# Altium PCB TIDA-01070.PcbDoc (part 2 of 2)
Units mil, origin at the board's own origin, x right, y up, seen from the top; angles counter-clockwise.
Board outline 4200 x 3450 mil, 4 copper layers (Top Layer, Signal Layer 1, Signal Layer 2, Bottom Layer), stack 61.668 mil thick; 155 components, 69 nets, 375 pads, 212 vias.
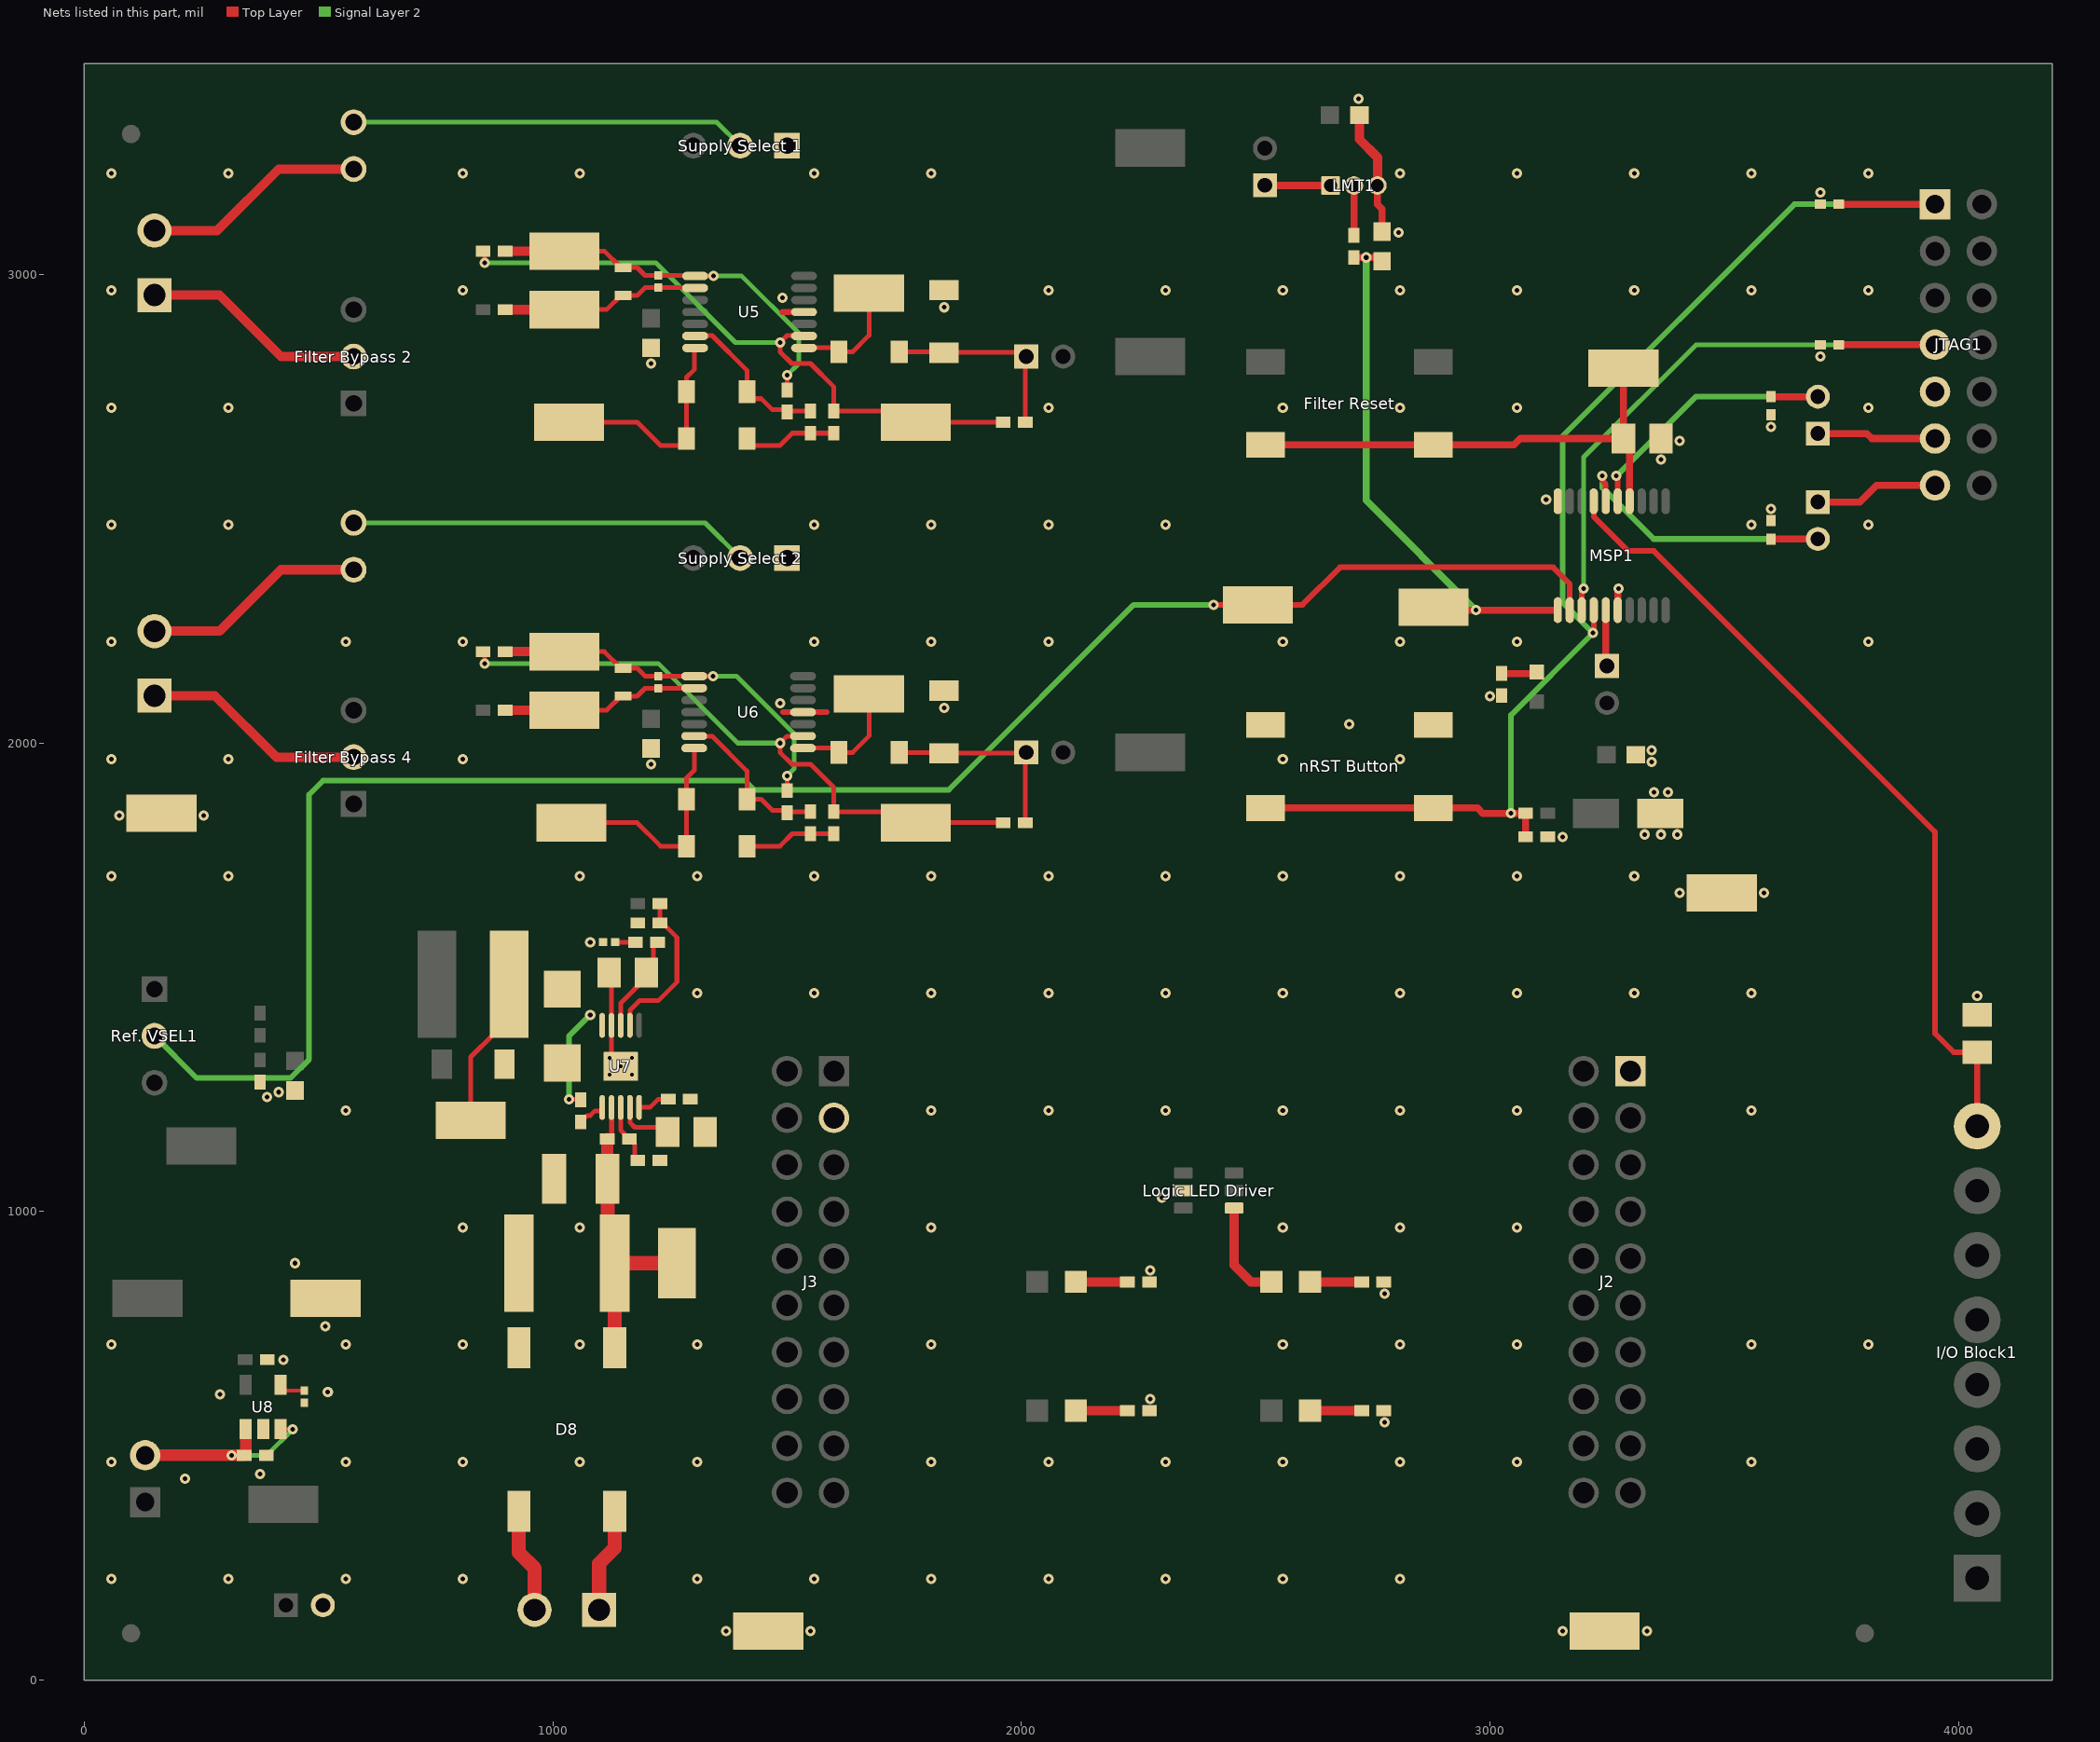
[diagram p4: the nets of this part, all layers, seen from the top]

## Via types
v1: diameter 22, hole 10, Top Layer to Bottom Layer, tented both sides, 206 vias
v2: diameter 19.68, hole 7.87, Top Layer to Bottom Layer, 5 vias
v3: diameter 36, hole 16, Top Layer to Bottom Layer, tented both sides, 1 vias

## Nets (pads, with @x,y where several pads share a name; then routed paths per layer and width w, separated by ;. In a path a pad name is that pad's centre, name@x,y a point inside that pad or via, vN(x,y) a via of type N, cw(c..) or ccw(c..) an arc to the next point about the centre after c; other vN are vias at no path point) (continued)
GND: "1.65V GND.1" "Logic LED Driver.2" "LP2985 GND.1" "nRST Button.1" "nRST Button.2" "Supply Select 1.1" "Supply Select 2.1" "TP GND.1" C1.2 C2.2 C3.1 C4.1 C5.1 C6.2 C7.1 C8.1 C9.1 C10.2 C12.1 C14.2 C16.2 C17.2 C18.2 C19.2 C20.2 C21.2 C22.2 D1.2 D8.2 J1.2 J2.1 J3.3 JTAG1.9 LMT1.3 MSP1.6 MSP1.20 MSP_GND.1 R2.2 R3.2 R4.2 R5.2 R7.2 R8.2 R24.1 R25.1 R30.1 R32.1 R33.1 TP3.1 U1.2 U2.2 U3.2 U4.2 U5.11 U6.11 U7.9 U7.11 U8.2 | length 663.9
  Top Layer w10: C19.2@1125.31,1510 1125.31,1329.69 v2(1145,1310)
  Top Layer w12: 1490,2920 U5.11@1536.14,2920 ; 1491,2066 1585,2066 ; v1@3272.8,2327.8 v1(3275,2330)
  Top Layer w15: LMT1.3@2760,3190 2760,3150 2770,3140 C5.1@2770,3091.5 ; MSP1.6@3272.8,2283.86 v1@3272.8,2327.8
  Top Layer w20: C4.1@2721.5,3340 2721.5,3288.5 2760,3250 LMT1.3@2760,3190
  other v1: 1370,105 1550,105 3155,105 3335,105 58,216 308,216 558,216 808,216 1308,216 1558,216 1808,216 2058,216 2308,216 2558,216 2808,216 215,430 375,440 58,466 558,466 808,466 1058,466 1308,466 1808,466 2058,466 2308,466 2558,466 2808,466 3058,466 3558,466 2775,550 2275,600 290,610 520,615 425,684 58,716 558,716 808,716 1058,716 1308,716 1808,716 2558,716 2808,716 3058,716 3558,716 3808,716 515,755 2775,825 2275,875 450,890 808,966 1058,966 1808,966 2558,966 2808,966 3058,966 2300,1030 558,1216 1808,1216 2058,1216 2308,1216 2558,1216 2808,1216 3058,1216 3558,1216 390,1245 415,1255 4040,1460 1308,1466 1558,1466 1808,1466 2058,1466 2308,1466 2558,1466 2808,1466 3058,1466 3308,1466 3558,1466 1080,1575 3405,1680 3585,1680 58,1716 308,1716 1058,1716 1308,1716 1558,1716 1808,1716 2058,1716 2308,1716 2558,1716 2808,1716 3058,1716 3308,1716 3155,1800 3330,1805 3365,1805 3400,1805 75,1845 255,1845 3350,1895 3380,1895 1210,1955 3345,1960 58,1966 308,1966 808,1966 2558,1966 2808,1966 3345,1985 2700,2040 1835,2075 1485,2085 3000,2100 58,2216 558,2216 808,2216 1558,2216 1808,2216 2058,2216 2558,2216 2808,2216 3058,2216 3808,2216 58,2466 308,2466 1558,2466 1808,2466 2058,2466 2308,2466 3558,2466 3808,2466 3600,2500 3120,2520 3365,2605 3405,2645 3600,2675 58,2716 308,2716 2058,2716 2558,2716 2808,2716 3058,2716 3808,2716 1210,2810 3705,2825 1835,2930 1490,2950 58,2966 808,2966 2058,2966 2308,2966 2558,2966 2808,2966 3058,2966 3308,2966 3558,2966 3808,2966 2805,3090 3705,3175 58,3216 308,3216 808,3216 1058,3216 1558,3216 1808,3216 2808,3216 3058,3216 3308,3216 3558,3216 3808,3216 2720,3375
  other v2: 1121.38,1292.28 1168.62,1292.28 1121.38,1327.72 1168.62,1327.72
NetC2_1: "Power Jumper1.2" C2.1 U8.1 U8.3 | length 447.2
  Top Layer w10: C2.1@341.38,480 C2.1@344.6,483.22 ; U8.3@419.4,535.76 420.16,535 v1(445,535)
  Top Layer w25: 130,480 v1(315,480) C2.1@341.38,480 ; C2.1@344.6,483.22 U8.1@344.6,535.76
  Signal Layer 2 w10: v1(315,480) 390,480 v1(445,535)
NetC10_1: "Filter Output 1.1" C10.1 D3.1 R13.2 | length 421.2
  Top Layer w10: D3.1@1739.47,2835 1823.62,2835 1825,2833.62 2009.25,2833.62 ; R13.2@2008.62,2685 2008.62,2832.99 2009.25,2833.62 ; 2010.63,2835 2009.25,2833.62
NetC11_1: C11.1 R10.1 R15.1 R16.2 TP18.1 U5.1 | length 829.3
  Top Layer w10: TP18.1@1025,3050 1110,3050 1145,3015 1180,3015 1197.01,2997.99 C11.1@1225,2997.99 1225.22,2997.77 U5.1@1301.86,2997.77 ; U5.1@1303.86,2996.77 v1(1343.23,2996.77) v1@1345,2995 ; R10.1@1500,2755 v1(1500,2785)
  Top Layer w20: R15.1@898.62,3050 TP18.1@1025,3050
  Signal Layer 2 w10: v1(1343.23,2996.77) 1403.23,2996.77 1525,2875 1525,2810 v1(1500,2785)
NetC11_2: C11.2 R14.2 R16.1 TP19.1 U5.2 | length 422.8
  Top Layer w10: TP19.1@1025,2925 1115,2925 1145,2955 1180,2955 1197.01,2972.01 C11.2@1225,2972.01 1301.68,2972.01 U5.2@1301.86,2972.18
  Top Layer w20: R14.2@898.62,2925 TP19.1@1025,2925
NetC13_1: C13.1 U7.1 | length 54.8
  Top Layer w10: C13.1@1060,1191.38 1073.62,1205 1080,1205 1090,1215 U7.1@1105,1215
NetC13_2: C13.2 D1.1 L1.1 TP2.1 U7.10 | length 429.9
  Top Layer w10: TP2.1@825,1195 825,1330 L1.1@875,1380 ; v1(1035,1240) 1058.62,1240 C13.2@1060,1238.62
  Signal Layer 2 w12: v1(1035,1240) 1035,1375 v1(1080,1420)
NetC14_1: "Filter Output 2.1" C14.1 D5.1 R20.2 | length 421.2
  Top Layer w10: D5.1@1739.47,1980 1823.62,1980 1825,1978.62 2009.25,1978.62 ; R20.2@2008.62,1830 2008.62,1977.99 2009.25,1978.62 ; 2010.63,1980 2009.25,1978.62
NetC15_1: C15.1 R17.1 R22.1 R26.2 TP23.1 U6.1 | length 814.6
  Top Layer w10: TP23.1@1025,2195 1110,2195 1145,2160 1180,2160 1197.01,2142.99 C15.1@1225,2142.99 1225.22,2142.77 U6.1@1301.86,2142.77 v1(1342.23,2142.77) v1@1345,2140 ; R17.1@1500,1903.62 R17.1@1501.38,1905 ; R17.1@1500,1906.38 v1(1500,1930)
  Top Layer w20: R22.1@898.62,2195 TP23.1@1025,2195
  Signal Layer 2 w10: v1(1342.23,2142.77) 1392.23,2142.77 1515,2020 1515,1945 v1(1500,1930)
NetC15_2: C15.2 R21.1 R26.1 TP24.1 U6.2 | length 422.8
  Top Layer w10: TP24.1@1025,2070 1115,2070 1145,2100 1180,2100 1197.01,2117.01 C15.2@1225,2117.01 1301.68,2117.01 U6.2@1301.86,2117.18
  Top Layer w20: R21.1@898.62,2070 TP24.1@1025,2070
NetC17_1: C17.1 C22.1 D8.1 R29.2 TP1.1 U7.2 | length 655.9
  Top Layer w10: C17.1@1116.38,1070.71 C17.1@1117.09,1070 ; R29.2@1116.38,1155 R29.2@1125.31,1163.94 ; C22.1@1117.09,905.28 C22.1@1132.36,890
  Top Layer w11: R29.2@1125.31,1163.94 U7.2@1125.31,1222.4
  Top Layer w25: C17.1@1116.38,1070.71 R29.2@1116.38,1155
  Top Layer w30: C22.1@1117.09,905.28 C17.1@1117.09,1070 ; D8.1@1132.36,709.5 C22.1@1132.36,890 TP1.1@1265,890
NetC18_1: C18.1 U7.4 | length 118.7
  Top Layer w10: U7.4@1164.68,1222.4 1164.68,1190.32 1175,1180 1240,1180 C18.1@1245,1185
NetC19_1: C19.1 R31.2 U7.8 | length 215
  Top Layer w10: U7.8@1145,1397.6 1145,1445 1200,1500 C19.1@1200,1510 1215,1525 1215,1575 R31.2@1223.62,1575
NetC20_1: C20.1 R31.1 | length 43.4
  Top Layer w10: C20.1@1132.99,1575 R31.1@1176.38,1575
NetC21_1: C21.1 U8.4 | length 55.7
  Top Layer w8: U8.4@419.4,630.24 431.65,617.99 C21.1@470,617.99
NetD2_1: D2.1 R10.2 R11.1 U5.6 | length 350.4
  Top Layer w10: U5.6@1301.86,2869.82 1340.18,2869.82 1414.47,2795.53 1414.47,2735 1445,2735 1468.62,2711.38 1500,2711.38 1502.76,2708.62 R11.1@1550,2708.62
NetD2_2: D2.2 D4.1 TP15.1 U5.7 | length 422.2
  Top Layer w10: TP15.1@1100,2685 1180,2685 1230,2635 1285.53,2635 1285.53,2735 1285.53,2780.53 1301.86,2796.86 U5.7@1301.86,2844.23
NetD3_2: D3.2 TP16.1 U5.8 | length 249.2
  Top Layer w10: U5.8@1534.14,2844.23 1601.3,2844.23 D3.2@1610.53,2835 1640,2835 1675,2870 TP16.1@1675,2960
NetD4_2: D4.2 R11.2 R12.1 | length 196.5
  Top Layer w10: D4.2@1414.47,2635 1485,2635 1511.38,2661.38 R12.1@1600,2661.38
NetD5_2: D5.2 TP21.1 U6.8 | length 249.2
  Top Layer w10: U6.8@1534.14,1989.23 1601.3,1989.23 D5.2@1610.53,1980 1640,1980 1675,2015 TP21.1@1675,2105
NetD6_1: D6.1 R17.2 R18.1 U6.6 | length 350.4
  Top Layer w10: U6.6@1301.86,2014.82 1340.18,2014.82 1414.47,1940.53 D6.1@1414.47,1880 1445,1880 1468.62,1856.38 1500,1856.38 1502.76,1853.62 R18.1@1550,1853.62
NetD6_2: D6.2 D7.1 TP20.1 U6.7 | length 422.2
  Top Layer w10: TP20.1@1100,1830 1180,1830 1230,1780 D7.1@1285.53,1780 D6.2@1285.53,1880 1285.53,1925.53 1301.86,1941.86 U6.7@1301.86,1989.23
NetD7_2: D7.2 R18.2 R19.1 | length 196.5
  Top Layer w10: D7.2@1414.47,1780 1485,1780 1511.38,1806.38 R19.1@1600,1806.38
NetD8_3: "Power Terminal Header1.2" D8.3 | length 224.4
  Top Layer w30: D8.3@927.64,360.5 927.64,272.36 961.1,238.9 961.1,150
NetD8_4: "Power Terminal Header1.1" D8.4 | length 224.4
  Top Layer w30: 1098.9,150 1098.9,248.9 1132.36,282.36 D8.4@1132.36,360.5
"NetDirty Coil LED1_2": "Dirty Coil LED1.2" R4.1 | length 110
  Top Layer w20: 2116.34,575 R4.1@2226.38,575
"NetDirty Filter LED1_2": "Dirty Filter LED1.2" R5.1 | length 110
  Top Layer w20: 2616.34,575 R5.1@2726.38,575
"NetFilter Bypass 1_2": "Filter Bypass 1.2" "Supply Select 1.2" | length 845.7
  Signal Layer 2 w10: 575,3325 1350,3325 1400,3275
"NetFilter Bypass 3_2": "Filter Bypass 3.2" "Supply Select 2.2" | length 856.1
  Signal Layer 2 w10: 575,2470 1325,2470 1400,2395
"NetFilter Reset_1": "Filter Reset.1" "Filter Reset.2" "Set Filter.1" MSP1.14 R24.2 | length 1059.2
  Top Layer w15: 2520.87,2636.42 2879.13,2636.42 3051.42,2636.42 3065,2650 R24.2@3285,2650 ; 3285,2800 R24.2@3285,2650 ; MSP1.14@3298.39,2516.14 3298.39,2636.61 R24.2@3285,2650
NetLMT1_1: "LMT84 V+.1" LMT1.1 | length 140.3
  Top Layer w15: 2520,3190.63 2520.63,3190 LMT1.1@2660,3190
NetLMT1_2: LMT1.2 R6.1 | length 106.4
  Top Layer w15: R6.1@2710,3083.62 LMT1.2@2710,3190
"NetLow Temp LED1_2": "Low Temp LED1.2" R3.1 | length 110
  Top Layer w20: 2116.34,850 R3.1@2226.38,850
NetMSP1_5: "MSP V+.1" MSP1.5 | length 120.6
  Top Layer w15: MSP1.5@3247.2,2283.86 3247.2,2167.17 3250,2164.37
NetPower_1: Power.1 R8.1 | length 76.2
  Top Layer w15: R8.1@3025,2148.62 3097.13,2148.62 Power.1@3100,2151.5
NetR7_1: "System Ok LED1.2" R7.1 | length 110
  Top Layer w20: 2616.34,850 R7.1@2726.38,850
NetR12_2: R12.2 R13.1 R15.2 TP17.1 U5.9 | length 1370.8
  Top Layer w10: R15.2@851.38,3050 855,3046.38 v1(855,3025) ; U5.9@1534.14,2869.82 1499.82,2869.82 v1(1485,2855) 1485,2835 1510,2810 1550,2810 1600,2760 R12.2@1600,2708.62 1751.38,2708.62 TP17.1@1775,2685 R13.1@1961.38,2685
  Signal Layer 2 w10: v1(855,3025) 1220,3025 1390,2855 v1(1485,2855)
NetR19_2: R19.2 R20.1 R22.2 TP22.1 U6.9 | length 1370.8
  Top Layer w10: R22.2@851.38,2195 855,2191.38 v1(855,2170) ; U6.9@1534.14,2014.82 1499.82,2014.82 v1(1485,2000) 1485,1980 1510,1955 1550,1955 1600,1905 R19.2@1600,1853.62 1751.38,1853.62 TP22.1@1775,1830 R20.1@1961.38,1830
  Signal Layer 2 w10: v1(855,2170) 1225,2170 1395,2000 v1(1485,2000)
NetR28_1: R28.1 R30.2 U7.7 | length 341.2
  Top Layer w10: U7.7@1164.68,1397.6 1164.68,1429.68 1185,1450 1225,1450 1265,1490 1265,1585 1235,1615 1228.62,1615 R28.1@1228.62,1655
NetR29_1: R29.1 R32.2 U7.3 | length 127.5
  Top Layer w10: U7.3@1145,1222.4 1145,1173.62 R29.1@1163.62,1155 1175,1143.62 1175,1116.38 R32.2@1181.38,1110
NetR33_2: R33.2 U7.5 | length 69.3
  Top Layer w10: U7.5@1184.37,1222.4 1207.4,1222.4 1225,1240 R33.2@1246.38,1240
NRST: "nRST Button.3" "nRST Button.4" C8.2 JTAG1.1 MSP1.4 R9.1 U4.1 | length 2769.5
  Top Layer w12: v1@3221.61,2236.61 MSP1.4@3221.61,2283.86
  Top Layer w15: 2520.87,1861.42 2879.13,1861.42 2973.58,1861.42 2985,1850 R9.1@3076.38,1850 C8.2@3076.38,1800 ; v1(3220,2235) v1@3221.61,2236.61 ; U4.1@3744.69,3150 JTAG1.1@3950,3150
  Signal Layer 2 w12: v1(3045,1850) 3045,2060 v1(3220,2235) 3155,2300 3155,2655 3650,3150 JTAG1.1@3950,3150
REFERENCE_SELECTOR: "Ref. VSEL1.2" MSP1.2 Reference.1 | length 3927.1
  Top Layer w12: v1(2410,2295) Reference.1@2505,2295 2600,2295 2680,2375 3135,2375 3170.43,2339.57 MSP1.2@3170.43,2283.86
  Signal Layer 2 w12: 150,1375 240,1285 440,1285 480,1325 480,1890 510,1920 1410,1920 1430,1900 1845,1900 2240,2295 2310,2295 v1(2410,2295)
SENSOR_OUT_1: "External Sensor Terminal1.2" "Filter Bypass 1.1" | length 479.3
  Top Layer w20: 150,3093.9 283.9,3093.9 415,3225 575,3225
SENSOR_OUT_2: "External Sensor Terminal2.2" "Filter Bypass 3.1" | length 479.3
  Top Layer w20: 150,2238.9 288.9,2238.9 420,2370 575,2370
SENSOR_RETURN_1: "External Sensor Terminal1.1" "Filter Bypass 2.2" | length 479.3
  Top Layer w20: 150,2956.1 288.9,2956.1 420,2825 575,2825
SENSOR_RETURN_2: "External Sensor Terminal2.1" "Filter Bypass 4.2" | length 479.3
  Top Layer w20: 150,2101.1 278.9,2101.1 410,1970 575,1970
SYSTEM_OK_OUT: "Logic LED Driver.4" "System Ok LED1.1" | length 216.1
  Top Layer w20: 2454.13,1007.6 2454.13,885.87 2490,850 2533.66,850
SYSTEM_ON: "I/O Block1.8" MSP1.17 R25.2 | length 1734.4
  Top Layer w12: MSP1.17@3221.61,2516.14 3221.61,2483.39 3295,2410 3350,2410 3950,1810 3950,1380 3990,1340 R25.2@4040,1340 4040,1182.28
TEMP_SENSOR: C5.2 MSP1.1 R6.2 Temp.1 | length 1180.1
  Top Layer w15: R6.2@2710,3036.38 v1(2736.06,3036.38) 2762.13,3036.38 C5.2@2770,3028.5 ; Temp.1@2880,2290 2886.14,2283.86 v1(2970,2283.86) MSP1.1@3144.84,2283.86
  Signal Layer 2 w15: v1(2736.06,3036.38) 2736.06,2517.8 v1(2970,2283.86)
TEST: JTAG1.7 MSP1.3 U3.1 | length 1382.5
  Top Layer w10: v1@3196.02,2326.02 v1(3200,2330)
  Top Layer w12: MSP1.3@3196.02,2283.86 v1@3196.02,2326.02
  Top Layer w15: U3.1@3744.69,2850 JTAG1.7@3950,2850
  Signal Layer 2 w10: v1(3200,2330) 3200,2610 3440,2850 JTAG1.7@3950,2850
UART_IN: JTAG1.13 UART_RX_Jumper1.1 | length 264.8
  Top Layer w15: UART_RX_Jumper1.1@3700,2514.37 3789.37,2514.37 3825,2550 JTAG1.13@3950,2550
UART_OUT: JTAG1.11 UART_TX_Jumper1.1 | length 254.4
  Top Layer w15: UART_TX_Jumper1.1@3700,2660.63 3804.37,2660.63 3815,2650 JTAG1.11@3950,2650
UART_RX: MSP1.16 U1.1 UART_RX_Jumper1.2 | length 688.2
  Top Layer w12: v1(3240,2570) 3240,2560 3247.2,2552.8 MSP1.16@3247.2,2516.14 ; U1.1@3609.37,2435 3610,2435.63
  Top Layer w15: U1.1@3600,2435.32 3600.31,2435.63 3610,2435.63 UART_RX_Jumper1.2@3700,2435.63
  Signal Layer 2 w12: v1(3240,2570) 3240,2545 3349.37,2435.63 UART_RX_Jumper1.2@3700,2435.63
UART_TX: MSP1.15 U2.1 UART_TX_Jumper1.2 | length 655.3
  Top Layer w12: v1(3270,2570) 3272.8,2567.2 MSP1.15@3272.8,2516.14
  Top Layer w15: U2.1@3600,2739.69 3600.31,2739.37 UART_TX_Jumper1.2@3700,2739.37
  Signal Layer 2 w12: v1(3270,2570) 3439.37,2739.37 UART_TX_Jumper1.2@3700,2739.37
pads on no net: FID1.1 FID2.1 FID3.1 H1.0 H2.0 H3.0 H4.0 J2.2 J2.3 J2.4 J2.5 J2.6 J2.7 J2.8 J2.9 J2.10 J2.12 J2.14 J2.16 J2.17 J2.18 J2.19 J2.20 J3.1 J3.6 J3.8 J3.9 J3.10 J3.11 J3.13 J3.14 J3.15 J3.16 J3.17 J3.18 J3.19 J3.20 JTAG1.2 JTAG1.3 JTAG1.5 JTAG1.6 JTAG1.8 JTAG1.10 JTAG1.12 JTAG1.14 SH-1.0 SH-2.0 SH-3.0 SH-4.0 SH-5.0 SH-6.0 SH-7.0 SH-8.0 SH-9.0 SH-10.0 SH-11.0 SH-12.0 SH-13.0 SH-14.0 U5.12 U5.13 U5.14 U6.12 U6.13 U6.14 U7.6

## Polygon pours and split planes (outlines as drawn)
NetC13_2 on Top Layer "Top Layer-No Net" (solid, remove dead copper, pour order 7): 1105,1385 1090,1385 1085,1385 1065,1405 1035,1435 995,1435 915,1435 910,1440 910,1535 960,1535 970,1525 1065,1525 1065,1480 1080,1465 1105,1440 1105,1420
GND on Top Layer "Top Layer-No Net" (solid, remove dead copper, pour order 8): 25,25 4175,25 4175,3425 25,3425
GND on Signal Layer 1 "Top Layer-No Net" (solid, remove dead copper, pour order 9): 25,25 4175,25 4175,3425 25,3425
GND on Bottom Layer "Top Layer-No Net" (solid, remove dead copper, pour order 10): 25,25 4175,25 4175,3425 25,3425

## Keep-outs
Keep-Out Layer:
  lines w10: -5,0 ccw(c0,0) 0,-5 ; -5,0 ccw(c0,0) 0,-5 ; -5,0 -5,3450 ; -5,3450 cw(c0,3450) 0,3455 ; -5,3450 cw(c0,3450) 0,3455 ; 0,-5 4200,-5 ; 0,3455 4200,3455 ; 4200,-5 ccw(c4200,0) 4205,0 ; 4200,-5 ccw(c4200,0) 4205,0 ; 4200,3455 cw(c4200,3450) 4205,3450 ; 4200,3455 cw(c4200,3450) 4205,3450 ; 4205,0 4205,3450
  text ".Layer_Name" at 577,-858.49 h60

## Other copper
Top Layer:
  pour cut-out: 1075.94,1365 1000.94,1365 961.56,1365 961.56,1355 1088.44,1355
  pour cut-out: 865,1342.5 865,1267.5 866.39,1267.5 875,1257.5 875,1355
  pour cut-out: 747.5,1150 672.5,1150 672.5,1148.61 662.5,1140 737.5,1140
  pour cut-out: 872.5,1615 797.5,1615 797.5,1613.61 787.5,1605 862.5,1605
  text ".Layer_Name" at 577,-858.49 h60
Signal Layer 1:
  text ".Layer_Name" at 577,-858.49 h60
Signal Layer 2:
  text ".Layer_Name" at 577,-858.49 h60
Bottom Layer:
  text ".Layer_Name" at 577,-858.49 h60

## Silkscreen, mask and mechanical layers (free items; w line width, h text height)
Top Overlay:
  region: 2865,1360 2565,1360 2565,1260 2865,1260
  text "'.PRJ_Number'.PCB_Rev-" at 1875,1275 h108.27
  text "5VDC  GND" at 325,55 h60
  text ".Layer_Name" at 577,-858.49 h60
Bottom Overlay:
  text ".Layer_Name" at 577,-858.49 h60
Top Paste:
  text ".Layer_Name" at 577,-858.49 h60
Bottom Paste:
  text ".Layer_Name" at 577,-858.49 h60
Top Solder:
  text ".Layer_Name" at 577,-858.49 h60
  text ".Layer_Name" at 577,-858.49 h60
Bottom Solder:
  text ".Layer_Name" at 577,-858.49 h60
Drill Guide:
  text ".Layer_Name" at 577,-858.49 h60
M1 Board Outline:
  the board outline again, w10
  text ".Layer_Name" at 577,-858.49 h60
M2 Board Dimensions:
  rectangle: 125,-400 500,-275
  rectangle: 0,-275 125,-150
  lines w7: 0,-275 1000,-275 ; 125,-400 125,-150 ; 250,-400 250,-150 ; 500,-400 500,-150 ; 750,-400 750,-150 ; 0,-400 0,-150 1000,-150 1000,-400 0,-400
  text ".Layer_Name" at 577,-858.49 h60
M3 3D STEP Top:
  text ".Layer_Name" at 577,-858.49 h60
M4 3D STEP Bottom:
  text ".Layer_Name" at 577,-858.49 h60
M5 Assembly Top:
  lines w10: -292,-930.17 6308,-930.17 ; -292,-726.83 6310,-726.83 ; -292,-523.5 -292,-1133.5 3713,-1133.5 6310,-1133.5 6310,-523.5 -291.5,-523.5 -291.5,-1133.5 1284,-1133.5 ; 2173,-1133.5 2173,-523.5 ; 3440,-726.83 3440,-523.5 ; 4280,-726.83 4280,-523.5 ; 4902,-1140 4902,-937.17
  text "COMPONENTS MARKED 'DNP' SHOULD NOT BE POPULATED." at 1153.5,-318.5 h60
  text "ASSEMBLY VARIANT:" at 1153,-434 h60
  text ".VariantName" at 2189,-434 h60
  text "PCB VIEWED FROM TOP SIDE" at -228.5,-655.67 h60
  text "BOARD #:" at 2248,-655.67 h60
  text ".PRJ_Number" at 2793.5,-655.67 h60
  text "REV:" at 3638,-655.67 h60
  text ".PCB_Rev" at 3929.5,-655.67 h60
  text "SVN REV:" at 4476,-655.67 h60
  text ".VersionControl_RevNumber" at 4982,-655.67 h60
  text "TID #:" at 2248,-859 h60
  text ".TID" at 2793.5,-859 h60
  text "PLOT NAME =" at -228.5,-1064.34 h60
  text ".plot_File_Name" at 577,-1064.34 h60
  text "GENERATED    :" at 2250,-1064.34 h60
  text ".Print_Date" at 3119.5,-1064.34 h60
  text ".Print_Time" at 3848.5,-1064.34 h60
  text "TEXAS INSTRUMENTS" at 5113,-1064.34 h60
M6 Assembly Bottom:
  lines w10: -292.5,-727.33 6309.5,-727.33 ; -290.5,-930.67 6309.5,-930.67 ; 1115.5,-1140.5 1115.5,-937.67 ; 1737.5,-727.33 1737.5,-524 ; 2577.5,-727.33 2577.5,-524 ; 3844.5,-1134 3844.5,-524 ; 4733.5,-1134 6309,-1134 6309,-524 -292.5,-524 -292.5,-1134 2304.5,-1134 6309.5,-1134 6309.5,-524
  text "COMPONENTS MARKED 'DNP' SHOULD NOT BE POPULATED." at 6102,-318 h60
  text ".VariantName" at 5058,-434 h60
  text "ASSEMBLY VARIANT:" at 6097,-434 h60
  text ".VersionControl_RevNumber" at 1035.5,-656.17 h60
  text "SVN REV:" at 1541.5,-656.17 h60
  text ".PCB_Rev" at 2088,-656.17 h60
  text "REV:" at 2379.5,-656.17 h60
  text ".PRJ_Number" at 3224,-656.17 h60
  text "BOARD #:" at 3769.5,-656.17 h60
  text "PCB VIEWED FROM BOTTOM SIDE" at 6246,-656.17 h60
  text ".TID" at 3224,-859.5 h60
  text "TID #:" at 3769.5,-859.5 h60
  text "TEXAS INSTRUMENTS" at 904.5,-1064.84 h60
  text ".Print_Time" at 2169,-1064.84 h60
  text ".Print_Date" at 2898,-1064.84 h60
  text "GENERATED    :" at 3767.5,-1064.84 h60
  text ".plot_File_Name" at 5440.5,-1064.84 h60
  text "PLOT NAME =" at 6246,-1064.84 h60
M9 Title Sheet:
  drawing of 57 lines, arcs and shapes, not listed
  text "1" at 739.84,8036.5 h70
  text "2" at 3235.5,8036.5 h70
  text "3" at 5724.84,8036.5 h70
  text "4" at 8231.51,8036.5 h70
  text "5" at 10730.5,8036.5 h70
  text "6" at 13235.5,8036.5 h70
  text "A" at -416.5,6893.5 h70
  text "A" at 14383.5,6893.5 h70
  text "B" at -416.5,4513.5 h70
  text "B" at 14383.5,4513.5 h70
  text "C" at -416.5,2138.5 h70
  text "C" at 14383.5,2138.5 h70
  text "PROJECT TITLE:" at 11343.5,277.5 h45
  text "TIDA-01070" at 11393.5,144.17 h70
  text "DESIGNED FOR:" at 11343.5,-23.5 h45
  text ".PRJ_Customer" at 11393.5,-163.5 h70
  text "D" at -416.5,-231.5 h70
  text "D" at 14383.5,-231.5 h70
  text "FILE NAME:" at 11343.5,-323.5 h45
  text "TIDA-01070" at 11393.5,-443.5 h70
  text "Texas Instruments (TI) and/or its licensors do not warrant the accuracy or completeness of this specification" at 6374,-605.34 h45
  text "ENGINEER:" at 11343.5,-613.5 h45
  text "LAYOUT BY:" at 12848.5,-613.5 h45
  text "or any information contained therein. TI and/or its licensors do not warrant that this design will meet" at 6329.01,-718 h45
  text "Brian Dempsey" at 11393.5,-768.49 h70
  text ".PCB_Layout" at 12899,-768.49 h70
  text "the specifications, will be suitable for your application or fit for any particular purpose, or will operate in" at 6329.01,-830.67 h45
  text ".Layer_Name" at 577,-858.49 h60
  text "ALTIUM DESIGNER VERSION:" at 12848.5,-923.5 h45
  text "an implementation. TI and/or its licensors do not warrant that the design is production worthy. You should" at 6329.01,-943.33 h45
  text "completely validate and test your design implementation to confirm the system functionality for your application." at 6374,-1056 h45
  text ".print_Scale" at 11393.5,-1056.83 h70
  text ".Application_BuildNumber" at 12899,-1056.83 h70
  text "1" at 739.84,-1263.5 h70
  text "2" at 3235.5,-1263.5 h70
  text "3" at 5724.84,-1263.5 h70
  text "4" at 8231.51,-1263.5 h70
  text "5" at 10730.5,-1263.5 h70
  text "6" at 13235.5,-1263.5 h70
M10 Fab Notes:
  drawing of 173 lines, arcs and shapes, not listed
  text "DESIGN INFORMATION" at 12378.02,6201 h60
  text "MIN. TRACK WIDTH:" at 11733.46,6021 h60
  text "8" at 12829.7,6021 h60
  text "MIL" at 12984.46,6021 h60
  text "MIN. CLEARANCE:" at 11733.46,5889 h60
  text "8" at 12769.7,5889 h60
  text "mm" at 12984.46,5889 h60
  text "MIN. VIA PAD SIZE:" at 11733.46,5757 h60
  text "22" at 12799.71,5757 h60
  text "MIL" at 12984.46,5757 h60
  text "0.05mm (2MIL)" at 12428.46,5615.29 h60
  text "MINIMUM ANNULAR RING" at 11404.23,5611 h60
  text "EXTERNAL" at 13136.46,5611 h60
  text "PER" at 11604.23,5493 h60
  text "IPC-D-275 CLASS 2 LEVEL C" at 11824.23,5493 h60
  text "MIL, HOLES" at 13312.46,5380.71 h60
  text "+/-" at 12920,5380 h60
  text "+/-" at 13774,5380 h60
  text "REGISTRATION TOLERANCES:" at 11404.23,5375 h60
  text "METAL" at 12604,5375 h60
  text "5" at 13180.2,5375 h60
  text "3" at 14013.2,5375 h60
  text "MIL" at 14129.46,5375 h60
  text "+/-" at 13774,5262 h60
  text "HOLE SIZE TOLERANCE (UNLESS OTHERWISE SPECIFIED):" at 11404.23,5257 h60
  text "3" at 14013.2,5257 h60
  text "MIL" at 14129.46,5257 h60
  text "MATERIAL:" at 11329.46,5047.54 h60
  text "FR-4 High Tg" at 12315.9,4907.21 h60
  text "FR-408" at 11750.46,4898.64 h60
  text "OTHER" at 13238.46,4898.64 h60
  text "X" at 12161,4895 h60
  text "62 MIL (1.6mm) +/-10%" at 12070.56,4735.92 h60
  text "THICKNESS:" at 11404.23,4731.64 h60
  text "X" at 11942.4,4731.64 h60
  text "OTHER" at 13355.46,4731.64 h60
  text "TOLERANCE:" at 11404.23,4573.64 h60
  text "X" at 12243.53,4573.64 h60
  text "ANSI IPC-6012 TYPE 3 CLASS 2" at 12430.48,4573.64 h60
  text "OTHER +/-" at 12430.46,4417.64 h60
  text "BOW & TWIST:" at 11404.23,4260.64 h60
  text "X" at 12243.53,4260.64 h60
  text "ANSI IPC-6012 TYPE 3 CLASS 2" at 12430.48,4260.64 h60
  text "OTHER +/-" at 12430.46,4102.13 h60
  text "DRILLING:" at 11329.46,3963.64 h60
  text "REFERENCE:" at 11404.23,3846.64 h60
  text "X" at 12052.46,3846.64 h60
  text "AS SHOWN" at 12239.46,3846.64 h60
  text "X" at 12953.46,3846.64 h60
  text "NC_DRILL FILES" at 13090.46,3846.64 h60
  text "PTH COPPER THICKNESS:" at 11404.23,3688.64 h60
  text "X" at 12534.46,3688.64 h60
  text "20-30 um" at 12671.46,3688.64 h60
  text "OTHER" at 13388.46,3688.64 h60
  text "BOARD FINISH:" at 11329.46,3529.64 h60
  text "SILKSCREEN:" at 11484.68,3411.64 h60
  text "X" at 12433.46,3411.64 h60
  text "TOP" at 12559.46,3411.64 h60
  text "BOTTOM" at 13070.46,3411.64 h60
  text "SILKSCREEN COLOR:" at 11484.68,3244.64 h60
  text "X" at 12432.42,3244.64 h60
  text "WHITE" at 12559.46,3244.64 h60
  text "OTHER" at 13070.46,3244.64 h60
  text "X" at 12563.42,3085.44 h60
  text "GREEN" at 12690.46,3085.44 h60
  text "OTHER" at 13308.46,3085.44 h60
  text "SOLDER RESIST COLOR:" at 11484.68,3074.64 h60
  text "X" at 12563.42,2915.44 h60
  text "MATTE" at 12690.46,2915.44 h60
  text "SEMI-GLOSS" at 13308,2914.8 h60
  text "IMMERSION GOLD (ENIG)" at 12390.46,2726.92 h60
  text "ENEPIG" at 13728,2723.64 h60
  text "SURFACE FINISH:" at 11329.46,2722.64 h60
  text "X" at 12203.51,2722.64 h60
  text "IMM. TIN/SILVER OR EQUIV" at 11659,2565.64 h60
  text "OTHER" at 13090.46,2565.64 h60
  text "ARRAY/PANEL:" at 11329.46,2386.64 h60
  text "CUT AND TRIM PER M1 BOARD OUTLINE" at 12390.46,2382.35 h60
  text "N.C. ROUTE" at 12390.46,2230.64 h60
  text "X" at 13069.46,2230.64 h60
  text "V. SCORE" at 13256.46,2230.64 h60
  text "CERTIFICATION:" at 11329.46,2093.64 h60
  text "MATERIALS AND WORKMANSHIP FOR ALL PCBS" at 12054.46,2093.64 h60
  text "TO MEET OR EXCEED THE REQUIREMENTS OF:" at 12054.46,1995.64 h60
  text "X" at 11680.96,1859.13 h60
  text "ANSI IPC-A-600F CLASS ->" at 11819.96,1859.13 h60
  text "X" at 13459.02,1859.13 h60
  text "2" at 13577.96,1859.14 h60
  text "1" at 13262.96,1857.64 h60
  text "3" at 13931.96,1857.64 h60
  text "X" at 12495.02,1699.64 h60
  text "RoHS" at 12631.96,1699.64 h60
  text "OTHER" at 13276.36,1699.64 h60
  text "PER ORDER" at 13673.42,1699.64 h60
  text "ALL BOARDS MUST MEET OR EXCEED UL94-V0 REQUIREMENTS." at 11357,1534 h60
  text "PCB MUST BEAR THE UL94V-0 UL REGISTERED MATERIAL ID NUMBER" at 11357,1414 h60
  text "ADDITIONAL REQUIREMENTS:" at 11329.46,1240.64 h60
  text "MICROSECTION:" at 11404.23,1125.64 h60
  text "YES" at 12309.96,1125.64 h60
  text "REQUIRED" at 13171.46,969.49 h60
  text "BARE BOARD ELEC. TEST:" at 11404.23,966.64 h60
  text "NONE" at 12709.96,966.64 h60
  text "X" at 13044.46,966.64 h60
  text "PER ORDER" at 13763.46,966.64 h60
  text ".Layer_Name" at 577,-858.49 h60
M11 Gerber Information:
  lines w10: -292,-930.17 6308,-930.17 ; -292,-726.83 6310,-726.83 ; -292,-523.5 -292,-1133.5 3713,-1133.5 6310,-1133.5 6310,-523.5 -291.5,-523.5 -291.5,-1133.5 1284,-1133.5 ; 2173,-1133.5 2173,-523.5 ; 3440,-726.83 3440,-523.5 ; 4280,-726.83 4280,-523.5 ; 4902,-1140 4902,-937.17
  text "ALL ARTWORK VIEWED FROM TOP SIDE" at -228.5,-655.67 h60
  text "BOARD #:" at 2248,-655.67 h60
  text ".PRJ_Number" at 2793.5,-655.67 h60
  text "REV:" at 3638,-655.67 h60
  text ".PCB_Rev" at 3929.5,-655.67 h60
  text "SVN REV:" at 4476,-655.67 h60
  text ".VersionControl_RevNumber" at 4982,-655.67 h60
  text "LAYER NAME =" at -228.5,-858.49 h60
  text "TID #:" at 2248,-859 h60
  text ".TID" at 2793.5,-859 h60
  text "PLOT NAME =" at -228.5,-1064.34 h60
  text ".plot_File_Name" at 577,-1064.34 h60
  text "GENERATED    :" at 2250,-1064.34 h60
  text ".Print_Date" at 3119.5,-1064.34 h60
  text ".Print_Time" at 3848.5,-1064.34 h60
  text "TEXAS INSTRUMENTS" at 5113,-1064.34 h60
M12 Stackup:
  drawing of 295 lines, arcs and shapes, not listed
  text "Layer" at 9717.5,7782.5 h60
  text "Name" at 10127.41,7782.5 h60
  text "Material" at 11067.15,7782.5 h60
  text "Thickness" at 11926.92,7782.5 h60
  text "Constant" at 12576.76,7782.5 h60
  text "Board Layer Stack" at 13146.62,7782.5 h60
  text "1" at 9717.5,7662.5 h60
  text "Top Overlay" at 10127.41,7662.5 h60
  text "2" at 9717.5,7542.5 h60
  text "Top Solder" at 10127.41,7542.5 h60
  text "Solder Resist" at 11067.15,7542.5 h60
  text "0.40mil" at 11926.92,7542.5 h60
  text "3.5" at 12576.76,7542.5 h60
  text "3" at 9717.5,7422.5 h60
  text "Top Layer" at 10127.41,7422.5 h60
  text "Copper" at 11067.15,7422.5 h60
  text "1.42mil" at 11926.92,7422.5 h60
  text "4" at 9717.5,7302.5 h60
  text "Dielectric1" at 10127.41,7302.5 h60
  text "FR-4 High TG" at 11067.15,7302.5 h60
  text "12.00mil" at 11926.92,7302.5 h60
  text "4.3" at 12576.76,7302.5 h60
  text "5" at 9717.5,7182.5 h60
  text "Signal Layer 1" at 10127.41,7182.5 h60
  text "Copper" at 11067.15,7182.5 h60
  text "1.42mil" at 11926.92,7182.5 h60
  text "6" at 9717.5,7062.5 h60
  text "Dielectric 2" at 10127.41,7062.5 h60
  text "FR-4 High TG" at 11067.15,7062.5 h60
  text "32.00mil" at 11926.92,7062.5 h60
  text "4.3" at 12576.76,7062.5 h60
  text "7" at 9717.5,6942.5 h60
  text "Signal Layer 2" at 10127.41,6942.5 h60
  text "Copper" at 11067.15,6942.5 h60
  text "1.42mil" at 11926.92,6942.5 h60
  text "8" at 9717.5,6822.5 h60
  text "Dielectric 3" at 10127.41,6822.5 h60
  text "FR-4 High TG" at 11067.15,6822.5 h60
  text "12.00mil" at 11926.92,6822.5 h60
  text "4.3" at 12576.76,6822.5 h60
  text "9" at 9717.5,6702.5 h60
  text "Bottom Layer" at 10127.41,6702.5 h60
  text "Copper" at 11067.15,6702.5 h60
  text "1.42mil" at 11926.92,6702.5 h60
  text "10" at 9717.5,6582.5 h60
  text "Bottom Solder" at 10127.41,6582.5 h60
  text "Solder Resist" at 11067.15,6582.5 h60
  text "0.40mil" at 11926.92,6582.5 h60
  text "3.5" at 12576.76,6582.5 h60
  text "11" at 9717.5,6462.5 h60
  text "Bottom Overlay" at 10127.41,6462.5 h60
  text ".Layer_Name" at 577,-858.49 h60
M13 Component Bodies Top:
  text ".Layer_Name" at 577,-858.49 h60
M14 Component Bodies Bottom:
  text ".Layer_Name" at 577,-858.49 h60
M15 Courtyards Top:
  text ".Layer_Name" at 577,-858.49 h60
M16 Courtyards Bottom:
  text ".Layer_Name" at 577,-858.49 h60
Drill Drawing:
  circle w10: c3625.62,5235.83 r20
  circle w10: c3625.62,5235.83 r33.33
  circle w10: c3625.62,4485.83 r33.33
  lines w10: 3592.29,4602.5 3658.96,4602.5 3658.96,4669.17 3592.29,4669.17 3592.29,4602.5 ; 3592.29,4752.5 3658.96,4752.5 3658.96,4819.17 3592.29,4819.17 3592.29,4752.5 ; 3592.29,4935.83 3625.62,4902.5 3658.96,4935.83 3625.62,4969.17 3592.29,4935.83 ; 3592.29,5119.17 3658.96,5119.17 3625.62,5052.5 3592.29,5119.17 ; 3592.29,5369.17 3608.96,5369.17 3608.96,5352.5 3642.29,5352.5 3642.29,5369.17 3658.96,5369.17 3658.96,5402.5 3642.29,5402.5 3642.29,5419.17 3608.96,5419.17 3608.96,5402.5 3592.29,5402.5 3592.29,5369.17 ; 3592.29,5569.17 3658.96,5569.17 3625.62,5502.5 3592.29,5569.17 ; 3592.29,5669.17 3608.96,5669.17 3625.62,5652.5 3642.29,5669.17 3658.96,5669.17 3642.29,5685.83 3658.96,5702.5 3642.29,5702.5 3625.62,5719.17 3608.96,5702.5 3592.29,5702.5 3608.96,5685.83 3592.29,5669.17 ; 3592.29,5802.5 3625.62,5819.17 3658.96,5802.5 3642.29,5835.83 3658.96,5869.17 3625.62,5852.5 3592.29,5869.17 3608.96,5835.83 3592.29,5802.5 ; 3592.29,5952.5 3625.62,5969.17 3658.96,5952.5 3642.29,5985.83 3658.96,6019.17 3625.62,6002.5 3592.29,6019.17 3608.96,5985.83 3592.29,5952.5 ; 3605.62,4615.83 3645.62,4615.83 3645.62,4655.83 3605.62,4655.83 3605.62,4615.83 ; 3605.62,5555.83 3645.62,5555.83 3625.62,5515.83 3605.62,5555.83 ; 3605.62,5965.83 3625.62,5975.83 3645.62,5965.83 3635.62,5985.83 3645.62,6005.83 3625.62,5995.83 3605.62,6005.83 3615.62,5985.83 3605.62,5965.83
  lines w15: 3532.5,4407.5 10642.57,4407.5 ; 3532.5,6057.5 10642.57,6057.5 ; 4083.38,4257.5 4083.38,6207.5 ; 4673.22,4257.5 4673.22,6207.5 ; 5772.9,4257.5 5772.9,6207.5 ; 6278.78,4257.5 6278.78,6207.5 ; 7012.58,4257.5 7012.58,6207.5 ; 8512.13,4257.5 8512.13,6207.5 ; 9101.98,4257.5 9101.98,6207.5 ; 9847.78,4257.5 9847.78,6207.5 ; 3532.5,4257.5 10642.57,4257.5 10642.57,6207.5 3532.5,6207.5 3532.5,4257.5
  text "Symbol" at 3622.5,6102.5 h72
  text "Count" at 4128.38,6102.5 h72
  text "Hole Size" at 4718.22,6102.5 h72
  text "Plated" at 5817.9,6102.5 h72
  text "Hole Type" at 6323.78,6102.5 h72
  text "Drill Layer Pair" at 7057.58,6102.5 h72
  text "Via/Pad" at 8557.13,6102.5 h72
  text "Pad Shape" at 9146.98,6102.5 h72
  text "Template" at 9892.78,6102.5 h72
  text "1" at 4128.38,5952.5 h60
  text "16.00mil (0.406mm)" at 4718.22,5952.5 h60
  text "PTH" at 5817.9,5952.5 h60
  text "Round" at 6323.78,5952.5 h60
  text "Top Layer - Bottom Layer" at 7057.58,5952.5 h60
  text "Via" at 8557.13,5952.5 h60
  text "Rounded" at 9146.98,5952.5 h60
  text "v91h41m0mx0" at 9892.78,5952.5 h60
  text "2" at 4128.38,5802.5 h60
  text "39.37mil (1.000mm)" at 4718.22,5802.5 h60
  text "PTH" at 5817.9,5802.5 h60
  text "Round" at 6323.78,5802.5 h60
  text "Top Layer - Bottom Layer" at 7057.58,5802.5 h60
  text "Pad" at 8557.13,5802.5 h60
  text "(Mixed)" at 9146.98,5802.5 h60
  text "(Mixed)" at 9892.78,5802.5 h60
  text "3" at 4128.38,5652.5 h60
  text "27.56mil (0.700mm)" at 4718.22,5652.5 h60
  text "PTH" at 5817.9,5652.5 h60
  text "Round" at 6323.78,5652.5 h60
  text "Top Layer - Bottom Layer" at 7057.58,5652.5 h60
  text "Pad" at 8557.13,5652.5 h60
  text "(Mixed)" at 9146.98,5652.5 h60
  text "(Mixed)" at 9892.78,5652.5 h60
  text "5" at 4128.38,5502.5 h60
  text "7.87mil (0.200mm)" at 4718.22,5502.5 h60
  text "PTH" at 5817.9,5502.5 h60
  text "Round" at 6323.78,5502.5 h60
  text "Top Layer - Bottom Layer" at 7057.58,5502.5 h60
  text "Via" at 8557.13,5502.5 h60
  text "Rounded" at 9146.98,5502.5 h60
  text "v50h20" at 9892.78,5502.5 h60
  text "6" at 4128.38,5352.5 h60
  text "47.24mil (1.200mm)" at 4718.22,5352.5 h60
  text "PTH" at 5817.9,5352.5 h60
  text "Round" at 6323.78,5352.5 h60
  text "Top Layer - Bottom Layer" at 7057.58,5352.5 h60
  text "Pad" at 8557.13,5352.5 h60
  text "(Mixed)" at 9146.98,5352.5 h60
  text "(Mixed)" at 9892.78,5352.5 h60
  text "8" at 4128.38,5202.5 h60
  text "50.00mil (1.270mm)" at 4718.22,5202.5 h60
  text "PTH" at 5817.9,5202.5 h60
  text "Round" at 6323.78,5202.5 h60
  text "Top Layer - Bottom Layer" at 7057.58,5202.5 h60
  text "Pad" at 8557.13,5202.5 h60
  text "(Mixed)" at 9146.98,5202.5 h60
  text "(Mixed)" at 9892.78,5202.5 h60
  text "14" at 4128.38,5052.5 h60
  text "31.50mil (0.800mm)" at 4718.22,5052.5 h60
  text "PTH" at 5817.9,5052.5 h60
  text "Round" at 6323.78,5052.5 h60
  text "Top Layer - Bottom Layer" at 7057.58,5052.5 h60
  text "Pad" at 8557.13,5052.5 h60
  text "(Mixed)" at 9146.98,5052.5 h60
  text "(Mixed)" at 9892.78,5052.5 h60
  text "14" at 4128.38,4902.5 h60
  text "40.00mil (1.016mm)" at 4718.22,4902.5 h60
  text "PTH" at 5817.9,4902.5 h60
  text "Round" at 6323.78,4902.5 h60
  text "Top Layer - Bottom Layer" at 7057.58,4902.5 h60
  text "Pad" at 8557.13,4902.5 h60
  text "(Mixed)" at 9146.98,4902.5 h60
  text "(Mixed)" at 9892.78,4902.5 h60
  text "19" at 4128.38,4752.5 h60
  text "35.43mil (0.900mm)" at 4718.22,4752.5 h60
  text "PTH" at 5817.9,4752.5 h60
  text "Round" at 6323.78,4752.5 h60
  text "Top Layer - Bottom Layer" at 7057.58,4752.5 h60
  text "Pad" at 8557.13,4752.5 h60
  text "(Mixed)" at 9146.98,4752.5 h60
  text "(Mixed)" at 9892.78,4752.5 h60
  text "40" at 4128.38,4602.5 h60
  text "45.28mil (1.150mm)" at 4718.22,4602.5 h60
  text "PTH" at 5817.9,4602.5 h60
  text "Round" at 6323.78,4602.5 h60
  text "Top Layer - Bottom Layer" at 7057.58,4602.5 h60
  text "Pad" at 8557.13,4602.5 h60
  text "(Mixed)" at 9146.98,4602.5 h60
  text "(Mixed)" at 9892.78,4602.5 h60
  text "206" at 4128.38,4452.5 h60
  text "10.00mil (0.254mm)" at 4718.22,4452.5 h60
  text "PTH" at 5817.9,4452.5 h60
  text "Round" at 6323.78,4452.5 h60
  text "Top Layer - Bottom Layer" at 7057.58,4452.5 h60
  text "Via" at 8557.13,4452.5 h60
  text "Rounded" at 9146.98,4452.5 h60
  text "v56h25m0mx0" at 9892.78,4452.5 h60
  text "318 Total" at 4128.38,4302.5 h60
  text ".Layer_Name" at 577,-858.49 h60
M17 Embedded Cavity:
  text ".Layer_Name" at 577,-858.49 h60
M18 Embedded Assembly:
  text ".Layer_Name" at 577,-858.49 h60
M19 Embedded Keepout:
  text ".Layer_Name" at 577,-858.49 h60

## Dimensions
0,0 to 0,3450 on M2 Board Dimensions
0,0 to 4200,0 on M2 Board Dimensions
0,-400 to 1000,-400 on M2 Board Dimensions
